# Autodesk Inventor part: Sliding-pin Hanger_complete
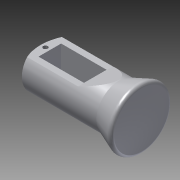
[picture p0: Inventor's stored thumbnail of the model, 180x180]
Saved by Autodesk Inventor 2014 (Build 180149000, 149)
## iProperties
Created: 2009-09
Part Number: Sliding-pin Hanger_complete
Document SubType Name: Modeling
Designer: sauflet
Density: 1 g/cm^3
Material: Generic
Appearance: Default
Author: sauflet
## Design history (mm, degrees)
sketch "Sketch1"
  geometry: L1 (0, 0)-(-114, 0); L2 (-107.301, 25)-(-25, 25); L3 (-25, 25)-(0, 35); L4 (0, 0)-(0, 35); A1 r 50 centre (-64, 0) between (-107.301, 25) and (-114, 0); 1 further point
  constraints: 8 end point, 2 point on circle, 1 centre point, 1 parallel, 1 perpendicular, 1 point on line, 1 vertical
  dimensions: "d0" = 35 distance of L3.end L1.start; "d5" = 25 horizontal distance of L2.end L3.end; "d6" = 114 distance of L1.start L1.end; "d9" = 25 vertical distance of L2.start L1.end; "d10" = 50 radius of A1
revolve "Revolution1" sketch "Sketch1" stored, may be unused: angle "d12" = 0 deg
sketch "Sketch2"
  geometry: L1 (-136.8, 0)-(22.8, 0) reference; L2 (-25, 25)-(-107.301, 25); L3 (-107.301, 25)-(-25, 25) reference; L4 (-111.371, 16)-(-51.371, 16); L5 (-111.371, 16)-(-51.371, 16); L6 (-51.371, 16)-(-25, 25); L7 (-25, -25)-(-107.301, -25); L8 (-107.301, -25)-(-25, -25); L9 (-111.371, -16)-(-51.371, -16); L10 (-111.371, -16)-(-51.371, -16); L11 (-51.371, -16)-(-25, -25); A1 r 50 centre (-64, 0) between (-107.301, 25) and (-107.301, -25) reference; A2 r 50 centre (-64, 0) between (-107.301, 25) and (-111.371, 16); A3 r 50 centre (-64, 0) between (-111.371, -16) and (-107.301, -25); 1 further point
  constraints: 18 end point, 7 symmetric about line, 5 point on circle, 2 centre point, 2 collinear, 2 concentric, 1 horizontal, 1 parallel, 1 other
  dimensions: "d22" = 60 distance of L4.start L4.end; "d27" = 9 vertical distance of L4.start L2.end
extrude "Extrusion1" cut sketch "Sketch2" stored distance "d28" = 81; taper "d29" = 0 deg
sketch "Sketch3"
  geometry: L1 (55.93, -38.419)-(55.93, 0) reference; L2 (55.93, -31.709)-(5.93, -31.709); L3 (5.93, -31.709)-(5.93, -6.709); L4 (5.93, -6.709)-(55.93, -6.709); L5 (55.93, -6.709)-(55.93, -31.709); 2 further points
  constraints: 8 end point, 2 parallel, 1 horizontal, 1 perpendicular, 1 point on line
  dimensions: "d30" = 50 distance of L3.end L4.end; "d31" = 25 distance of L2.end L3.end; "d34" = 6.71 vertical distance of point (0, -38.419) L2.end
extrude "Extrusion2" cut sketch "Sketch3" stored distance "d35" = 10; taper "d36" = 0 deg
fillet "Fillet1" dims "d37" = 3.25
body "Solid1"
workplane "Work Plane1"
hole "Hole1" diameter "d49" = 4.917; stored, may be unused: countersink angle "d53" = 90 deg, drill point angle "d55" = 118 deg; dims "d47" = 5, "d48" = 19, "d50" = 6, "d51" = 4, "d52" = 2, "d54" = 8
feature "Move Face1"
other parameters: "d19" = 38
